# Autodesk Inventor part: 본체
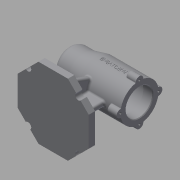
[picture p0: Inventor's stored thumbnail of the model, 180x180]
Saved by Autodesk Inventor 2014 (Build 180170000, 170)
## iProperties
Created: 2019-12
Part Number: 본체
Material: Generic
Document SubType Name: Modeling
Designer: kh
Density: 1 g/cm^3
Appearance: Default
Author: kh
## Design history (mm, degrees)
sketch "Sketch1"
  geometry: L1 (-56, 23.196)-(-23.196, 56); L2 (-23.196, 56)-(23.196, 56); L3 (23.196, 56)-(56, 23.196); L4 (56, 23.196)-(56, -23.196); L5 (56, -23.196)-(23.196, -56); L6 (23.196, -56)-(-23.196, -56); L7 (-23.196, -56)-(-56, -23.196); L8 (-56, -23.196)-(-56, 23.196); 3 further points
  constraints: 16 end point, 1 coincident, 1 horizontal alignment, 1 midpoint, 17 other
  dimensions: "d0" = 56 distance from line of L4 point (0, 0)
extrude "Extrusion1" new body sketch "Sketch1" distance "d1" = 10; taper "d2" = 0 deg
sketch "Sketch2"
  geometry: L1 (-23.196, 56)-(-56, 23.196) reference; C1 r 5 at (-39.598, 39.598); 1 further point
  constraints: 1 centre point, 1 midpoint
  dimensions: "d84" = 10 diameter of C1
extrude "Extrusion2" cut sketch "Sketch2" stored distance "d4" = 10; taper "d5" = 0 deg
pattern_circular "Circular Pattern1" dims angle "d7" = 360 deg
revolve "Revolution1" stored, may be unused: angle "d32" = 90 deg
fillet "Fillet1" dims "d33" = 3
sketch "Sketch5"
  geometry: A1 r 30 centre (0, 0) between (0, 30) and (5.97, 29.4) reference; A2 r 6 centre (0, 30) between (5.97, 29.4) and (-5.97, 29.4); 1 further point
  constraints: 5 point on circle, 1 centre point, 1 vertical alignment
  dimensions: "d34" = 6 radius of A2
extrude "Extrusion3" join sketch "Sketch5" distance "d35" = 16; taper "d36" = 0 deg
sketch "Sketch7"
  geometry: L1 (23.196, 10)-(-23.196, 10) reference; L2 (31, 10)-(31, 56); L3 (41, 56)-(-13, 56) reference; L4 (56, 0)-(56, 10) reference; L5 (-56, 0)-(-56, 10) reference; L6 (-38, 10)-(-16.55, 56); L7 (-43.134, 10)-(-56, 10) reference; L8 (31, 56)-(-16.55, 56); L9 (-38, 10)-(31, 10); 1 further point
  constraints: 8 end point, 3 perpendicular, 2 point on line, 1 parallel
  dimensions: "d37" = 25 distance between parallel lines of L4 L2; "d38" = 18 distance from line of L5 L6.start; "d39" = 115 deg angle of L7 L6
extrude "Extrusion4" join sketch "Sketch7" stored distance "d40" = 8; taper "d41" = 0 deg
sketch "Sketch8"
  geometry: L1 (10, -23.196)-(10, 23.196) reference; L2 (10, 23.196)-(10, 36.062) reference; L3 (10, -56)-(10, -43.134) reference; L4 (0, -56)-(10, -56) reference; L5 (10, -36)-(56.766, -18.979); L6 (10, -36)-(10, 36); L7 (0, 56)-(10, 56) reference; L8 (10, 43.134)-(10, 56) reference; L9 (10, 36)-(56.766, 18.979); L10 (56.766, 18.979)-(56.766, -18.979); A1 r 30 centre (80, 0) between (50.268, -4) and (50.268, 4) reference; A2 r 30 centre (80, 0) between (56.766, 18.979) and (56.766, -18.979); 1 further point
  constraints: 8 end point, 5 point on circle, 1 centre point, 1 coincident, 1 collinear, 1 vertical alignment
  dimensions: "d44" = 20 distance from line of L4 L5.start; "d45" = 20 distance from line of L7 L6.end; "d48" = 110 deg angle of L3 L5; "d49" = 110 deg angle of L8 L9
fillet "Fillet4" dims "d54" = 3
fillet "Fillet5" dims "d55" = 1
hole "Hole1" diameter "d58" = 3.242; stored, may be unused: countersink angle "d62" = 90 deg, drill point angle "d64" = 118 deg; dims "d56" = 10, "d57" = 10, "d59" = 8, "d60" = 4, "d61" = 2, "d63" = 11
pattern_circular "Circular Pattern2" dims "d66" = 360 deg
fillet "Fillet6" dims "d68" = 10
extrude "Extrusion6" join sketch "Sketch8" stored distance "d69" = 8; taper "d70" = 0 deg
fillet "Fillet7" dims "d71" = 3
fillet "Fillet8" dims "d72" = 3
fillet "Fillet9" dims "d73" = 0.3
fillet "Fillet10" dims "d74" = 3
sketch "Sketch10"
  geometry: L1 (79.196, 74.002)-(79.196, 85.998) reference; 3 further points
  constraints: 1 horizontal alignment, 1 midpoint, 1 other
  dimensions: "d75" = 41 distance of point (79.196, 80) point (38.196, 80)
emboss "Emboss1" sketch "Sketch10" dims "d76" = 0.5, "d77" = 0
fillet "Fillet11" dims "d80" = 3
chamfer "Chamfer1" distance "d81" = 1; stored, may be unused: second distance "d82" = 2, angle "d83" = 45 deg
body "Solid1"
sketch "Sketch4"
  geometry: L1 (-72.491, 80)-(124.7, 80); L2 (43.134, 0)-(34.598, 0) reference; L3 (-56, 80)-(-56, 105); L4 (-56, 105)-(-31, 105); L5 (-31, 105)-(-11, 110); L6 (-11, 110)-(56, 110); L7 (56, 110)-(56, 101); L8 (56, 101)-(41, 101); L9 (41, 101)-(41, 104); L10 (41, 104)-(-13, 104); L11 (-13, 104)-(-13, 101); L12 (-13, 101)-(-25, 101); L13 (-25, 101)-(-25, 97.5); L14 (-25, 97.5)-(-43, 97.5); L15 (-43, 97.5)-(-43, 96); L16 (-43, 96)-(-47, 96); L17 (-47, 96)-(-47, 90.5); L18 (-47, 90.5)-(-50, 90.5); L19 (-50, 90.5)-(-50, 80); L20 (-56, 80)-(-50, 80); 3 further points
  constraints: 38 end point, 9 perpendicular, 7 parallel, 2 point on line, 1 collinear, 1 horizontal, 1 vertical alignment
  dimensions: "d9" = 80 distance between parallel lines of L2 L1; "d10" = 60 diameter of L6 L1; "d11" = 50 diameter of L4 L1; "d13" = 21 diameter of L18 L1; "d16" = 42 diameter of L12 L1; "d18" = 35 diameter of L14 L1; "d19" = 32 diameter of L16 L1; "d20" = 48 diameter of L10 L1; "d21" = 42 diameter of L8 L1; "d22" = 25 distance of L3.end L4.end; "d23" = 45 horizontal distance of L3.end L5.end; "d25" = 3 distance of L17.end L18.end; "d26" = 4 distance of L15.end L16.end; "d27" = 18 distance of L13.end L14.end; "d28" = 12 distance of L11.end L12.end; "d29" = 54 distance of L9.end L10.end; "d30" = 15 distance of L7.end L8.end; "d31" = 112 distance between parallel lines of L3 L7
other parameters: "d46" = 110 deg
